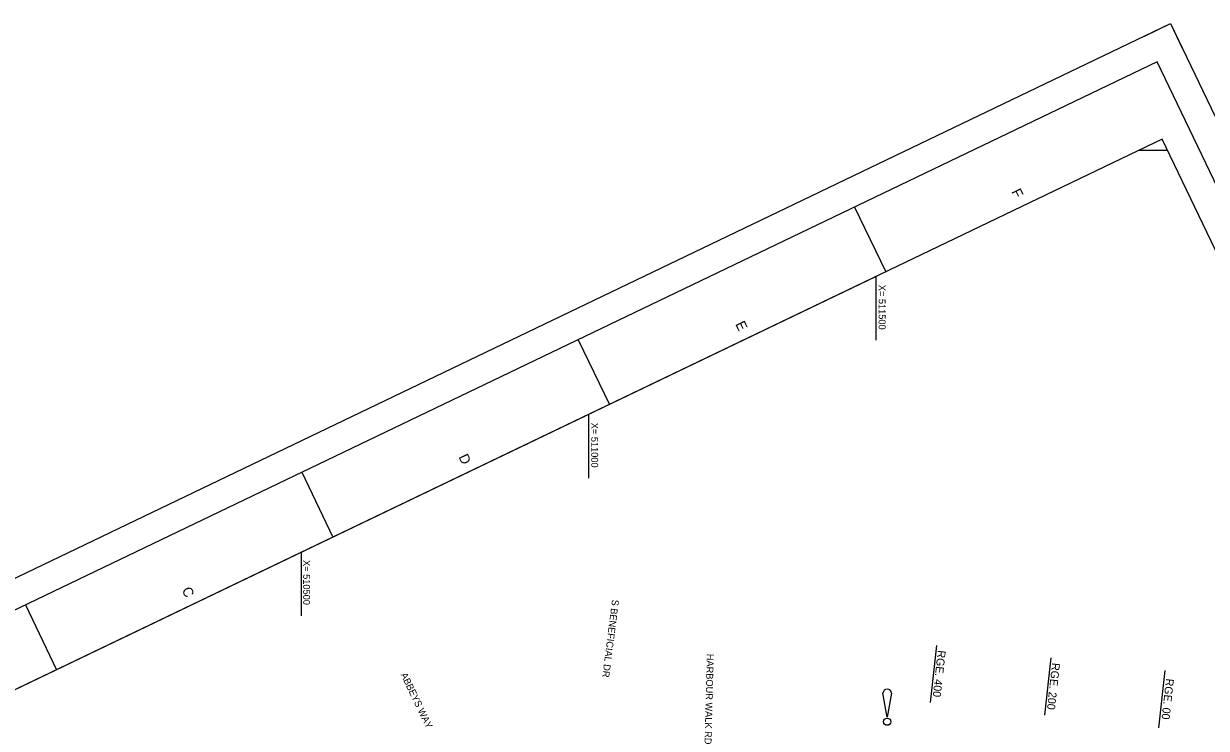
# Model space of a CAD drawing. Extents: x 508947 to 513916, y 1303283 to 1308721.
# Drawn here: x 510017 to 512074, y 1307494 to 1308721 of the extents above; entities that cross this region are included whole.
import ezdxf

# ---------------------------------------------------------------- set-up
doc = ezdxf.new("R2010")
doc.units = 0
for name, color, linetype in [('G-ANNO-NPLT', 7, 'Continuous'), ('G-ANNO-TTLB', 7, 'Continuous'), ('V-ALGN-TEXT', 7, 'Continuous'), ('V-CHAN-NAID', 7, 'Continuous'), ('V-CHAN-SYMB', 7, 'Continuous'), ('V-ROAD-IDEN', 7, 'Continuous'), ('V-TOPO-COOR-STAT', 7, 'Continuous')]:
    doc.layers.add(name, color=color, linetype=linetype)

msp = doc.modelspace()

# ---------------------------------------------------------------- linework, layer by layer
at = {"layer": 'G-ANNO-NPLT'}
msp.add_lwpolyline([(512011.7, 1308720.8), (513916.1, 1304754.3), (510851.1, 1303282.7), (508946.7, 1307249.2)], close=True, dxfattribs=at)
msp.add_lwpolyline([(511966.6, 1308699.2), (512011.7, 1308720.8), (512033.3, 1308675.7)], dxfattribs=at)
at = {"layer": 'G-ANNO-TTLB'}
for p, q in [((511462.3, 1308401.6), (511516.4, 1308288.9)), ((510981.5, 1308170.7), (511035.6, 1308058)), ((510500.7, 1307939.9), (510554.8, 1307827.2)), ((510020, 1307709.1), (510074.1, 1307596.4))]:
    msp.add_line(p, q, dxfattribs=at)
for points in [[(509013.4, 1307225.8), (510874.5, 1303349.5), (513849.4, 1304777.8), (511988.3, 1308654.1)], [(513782.7, 1304801.2), (511997.3, 1308519.8), (509112.6, 1307134.8), (510898, 1303416.2)]]:
    msp.add_lwpolyline(points, close=True, dxfattribs=at)
at = {"layer": 'V-ALGN-TEXT'}
for p, q in [((511594.1, 1307539.3), (511605.1, 1307638.7)), ((511792.9, 1307517.4), (511803.9, 1307616.8)), ((511991.7, 1307495.5), (512002.7, 1307594.9))]:
    msp.add_line(p, q, dxfattribs=at)
at = {"layer": 'V-CHAN-NAID'}
for p, q in [((511518.9, 1307513.9), (511511.5, 1307555.8)), ((511526.3, 1307555.8), (511518.9, 1307513.9))]:
    msp.add_line(p, q, dxfattribs=at)
msp.add_circle((511518.8, 1307505.9), 6.3, dxfattribs=at)
msp.add_arc((511518.9, 1307555.2), 7.42, 4.6442, 175.3545, dxfattribs=at)
at = {"layer": 'V-CHAN-SYMB'}
msp.add_line((511500, 1308281), (509112.6, 1307134.8), dxfattribs=at)
at = {"layer": 'V-TOPO-COOR-STAT'}
for p, q in [((512006.8, 1308500), (511956.1, 1308500)), ((511500, 1308170.1), (511500, 1308281)), ((511000, 1307930), (511000, 1308041)), ((510500, 1307690), (510500, 1307800.9))]:
    msp.add_line(p, q, dxfattribs=at)

# ---------------------------------------------------------------- texts
at = {"layer": 'G-ANNO-TTLB'}
for s, p in [('F', (511734.5, 1308428.5)), ('E', (511254.3, 1308198.1)), ('D', (510772.8, 1307966.8)), ('C', (510291.3, 1307735.4))]:
    msp.add_text(s, height=17.5, rotation=295.6468, dxfattribs=at).set_placement(p)
at = {"layer": 'V-ALGN-TEXT'}
for s, p in [('RGE. 400', (511607, 1307630.7)), ('RGE. 200', (511805.8, 1307608.8)), ('RGE. 00', (512004, 1307581.5))]:
    msp.add_text(s, height=13.92, rotation=263.7132, dxfattribs=at).set_placement(p)
at = {"layer": 'V-ROAD-IDEN'}
for s, rotation, p in [('S BENEFICIAL DR', 262.7319, (511040.5, 1307719)), ('HARBOUR WALK RD', 268.5305, (511205.2, 1307624.2)), ('ABBEYS WAY', 295.6468, (510672.2, 1307587.7))]:
    msp.add_text(s, height=12, rotation=rotation, dxfattribs=at).set_placement(p)
at = {"layer": 'V-TOPO-COOR-STAT'}
for s, p in [('X= 511500', (511504.1, 1308266.3)), ('X= 511000', (511004.1, 1308026.2)), ('X= 510500', (510502.9, 1307787.2))]:
    msp.add_text(s, height=12, rotation=270, dxfattribs=at).set_placement(p)

doc.saveas('drawing.dxf')
